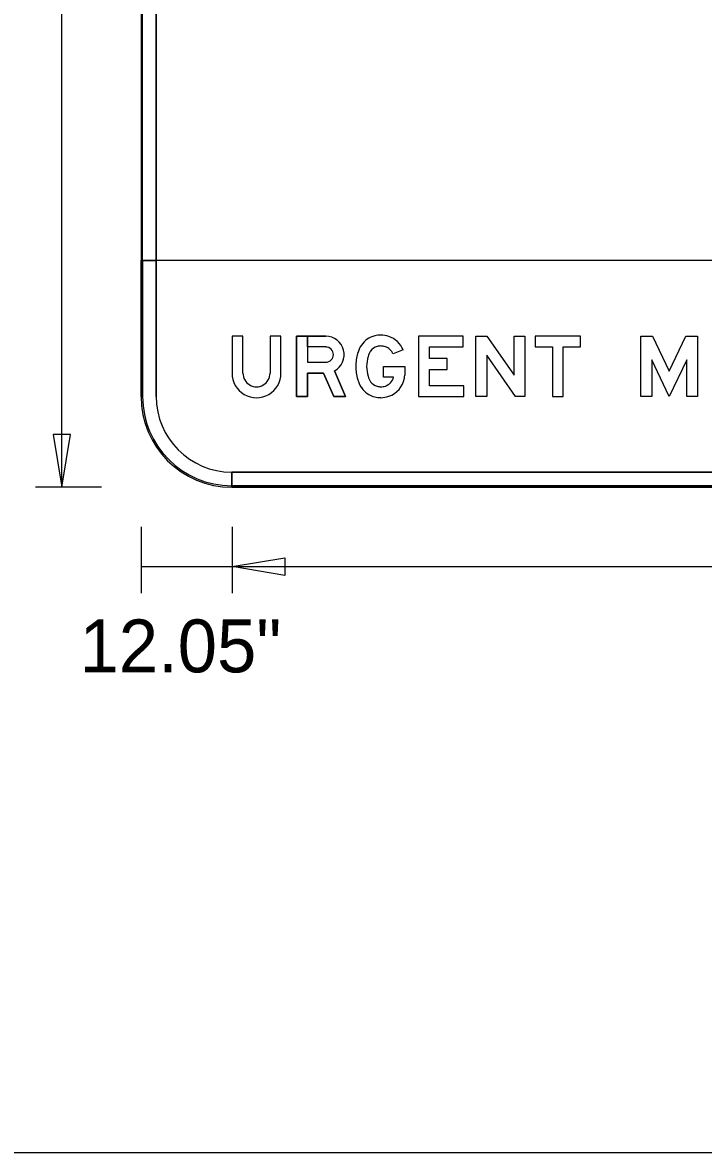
# Model space of a CAD drawing. Extents: x 17890484 to 17890754, y 17897495 to 17897992.
# Drawn here: x 17890527.22 to 17890534.74, y 17897525.52 to 17897537.98 of the extents above; entities that cross this region are included whole.
import ezdxf

# ---------------------------------------------------------------- set-up
doc = ezdxf.new("R2010")
doc.units = 0
for name, color, linetype in [('GSBWFill', 7, 'Continuous'), ('GSColorFill', 7, 'Continuous'), ('GSDims', 7, 'Continuous'), ('GSOutline', 7, 'Continuous'), ('SheetLinesMisc2_dp', 7, 'Continuous')]:
    doc.layers.add(name, color=color, linetype=linetype)

msp = doc.modelspace()

# ---------------------------------------------------------------- linework, layer by layer
at = {"layer": 'GSBWFill'}
for p, q in [((17890528.531, 17897541.854), (17890528.531, 17897533.854)), ((17890528.698, 17897533.854), (17890528.698, 17897541.854)), ((17890528.531, 17897533.854), (17890528.531, 17897535.354)), ((17890528.531, 17897535.354), (17890528.698, 17897535.354)), ((17890548.531, 17897535.354), (17890528.531, 17897535.354)), ((17890528.531, 17897535.354), (17890528.531, 17897533.854)), ((17890528.698, 17897535.354), (17890528.698, 17897535.187)), ((17890528.698, 17897535.187), (17890528.698, 17897533.854)), ((17890529.955, 17897534.521), (17890529.955, 17897534.112)), ((17890529.531, 17897532.854), (17890529.531, 17897533.021)), ((17890529.531, 17897533.021), (17890547.531, 17897533.021)), ((17890547.531, 17897533.021), (17890529.533, 17897533.021)), ((17890529.533, 17897533.021), (17890529.533, 17897532.854)), ((17890547.531, 17897532.854), (17890529.531, 17897532.854)), ((17890529.531, 17897532.854), (17890547.531, 17897532.854)), ((17890529.533, 17897532.854), (17890547.531, 17897532.854))]:
    msp.add_line(p, q, dxfattribs=at)
for points in [[(17890529.655, 17897534.112), (17890529.655, 17897534.521), (17890529.535, 17897534.521), (17890529.535, 17897534.112)], [(17890530.075, 17897534.112), (17890530.075, 17897534.521), (17890529.955, 17897534.521)], [(17890530.665, 17897534.138), (17890530.788, 17897533.854), (17890530.657, 17897533.854), (17890530.545, 17897534.114), (17890530.368, 17897534.114), (17890530.368, 17897533.854), (17890530.248, 17897533.854), (17890530.248, 17897534.521), (17890530.368, 17897534.521), (17890530.368, 17897534.234), (17890530.57, 17897534.234)], [(17890530.368, 17897534.401), (17890530.368, 17897534.521), (17890530.57, 17897534.521)], [(17890530.57, 17897534.401), (17890530.368, 17897534.401)], [(17890531.423, 17897534.37), (17890531.312, 17897534.325)], [(17890531.318, 17897534.067), (17890531.208, 17897534.067), (17890531.208, 17897534.187), (17890531.441, 17897534.187), (17890531.441, 17897534.091)]]:
    msp.add_lwpolyline(points, dxfattribs=at)
for points in [[(17890532.095, 17897533.974), (17890531.715, 17897533.974), (17890531.715, 17897534.153), (17890531.911, 17897534.153), (17890531.911, 17897534.273), (17890531.715, 17897534.273), (17890531.715, 17897534.401), (17890532.085, 17897534.401), (17890532.085, 17897534.521), (17890531.595, 17897534.521), (17890531.595, 17897533.854), (17890532.095, 17897533.854)], [(17890532.768, 17897534.521), (17890532.768, 17897533.854), (17890532.665, 17897533.854), (17890532.348, 17897534.311), (17890532.348, 17897533.854), (17890532.228, 17897533.854), (17890532.228, 17897534.521), (17890532.348, 17897534.521), (17890532.648, 17897534.089), (17890532.648, 17897534.521)], [(17890532.881, 17897534.401), (17890533.071, 17897534.401), (17890533.071, 17897533.854), (17890533.191, 17897533.854), (17890533.191, 17897534.401), (17890533.381, 17897534.401), (17890533.381, 17897534.521), (17890532.881, 17897534.521)], [(17890534.361, 17897534.134), (17890534.545, 17897534.521), (17890534.675, 17897534.521), (17890534.675, 17897533.854), (17890534.555, 17897533.854), (17890534.555, 17897534.261), (17890534.361, 17897533.854), (17890534.168, 17897534.261), (17890534.168, 17897533.854), (17890534.048, 17897533.854), (17890534.048, 17897534.521), (17890534.177, 17897534.521)]]:
    msp.add_lwpolyline(points, close=True, dxfattribs=at)
for centre, radius, start, end in [((17890530.57, 17897534.317), 0.203, 297.837, 90), ((17890530.57, 17897534.317), 0.0833, 270, 90), ((17890529.531, 17897533.854), 1, 180, 270), ((17890529.531, 17897533.854), 1, 180, 270), ((17890529.531, 17897533.854), 1, 180, 270), ((17890529.531, 17897533.854), 0.833, 180, 270), ((17890529.531, 17897533.854), 0.833, 180, 270)]:
    msp.add_arc(centre, radius, start, end, dxfattribs=at)
for centre, major_axis, start_param, end_param in [((17890531.165, 17897534.291), (0, 0.24), 0.229188, 0.990896), ((17890531.177, 17897534.243), (0, 0.289), 0, 0.229188), ((17890531.177, 17897534.252), (0, 0.28), 5.955089, 6.283185), ((17890531.183, 17897534.272), (0, 0.259), 5.097002, 5.955089), ((17890531.255, 17897534.232), (0, 0.348), 0.990896, 1.282161), ((17890531.165, 17897534.291), (0, 0.12), 0.229188, 0.990896), ((17890531.177, 17897534.243), (0, 0.169), 6.283185, 6.512373), ((17890531.177, 17897534.252), (0, 0.16), 5.955089, 6.283185), ((17890531.183, 17897534.272), (0, 0.139), 5.097002, 5.955089), ((17890531.406, 17897534.187), (0, 0.505), 1.282161, 1.570796), ((17890531.406, 17897534.187), (0, 0.385), 1.282161, 1.570796), ((17890531.255, 17897534.232), (0, 0.228), 0.990896, 1.282161), ((17890531.406, 17897534.187), (0, 0.505), 1.570796, 1.859431), ((17890531.406, 17897534.187), (0, 0.385), 1.570796, 1.859431), ((17890529.805, 17897534.112), (0, 0.27), 1.570796, 4.712389), ((17890529.805, 17897534.112), (0, 0.15), 1.570796, 4.712389), ((17890531.255, 17897534.143), (0, 0.348), 1.859431, 2.150696), ((17890531.255, 17897534.143), (0, 0.228), 1.859431, 2.150696), ((17890531.165, 17897534.084), (0, 0.12), 2.150696, 2.912405), ((17890531.183, 17897534.102), (0, 0.139), 3.469689, 4.457885), ((17890531.183, 17897534.102), (0, 0.259), 3.469689, 4.532209), ((17890531.243, 17897534.091), (0, 0.198), 4.532209, 4.712389), ((17890531.165, 17897534.084), (0, 0.24), 2.150696, 2.912405), ((17890531.177, 17897534.132), (0, 0.169), 2.912405, 3.141593), ((17890531.177, 17897534.122), (0, 0.16), 3.141593, 3.469689), ((17890531.177, 17897534.132), (0, 0.289), 2.912405, 3.141593), ((17890531.177, 17897534.122), (0, 0.28), 3.141593, 3.469689)]:
    msp.add_ellipse(centre, major_axis=major_axis, ratio=0.999994, start_param=start_param, end_param=end_param, dxfattribs=at)
at = {"layer": 'GSColorFill'}
for p, q in [((17890528.531, 17897541.854), (17890528.531, 17897533.854)), ((17890528.531, 17897541.854), (17890528.531, 17897533.854)), ((17890528.531, 17897541.854), (17890528.531, 17897533.854)), ((17890528.548, 17897533.854), (17890528.548, 17897541.854)), ((17890528.698, 17897533.854), (17890528.698, 17897541.854)), ((17890548.531, 17897535.354), (17890528.531, 17897535.354)), ((17890528.531, 17897535.354), (17890528.531, 17897533.854)), ((17890528.531, 17897533.854), (17890528.531, 17897535.354)), ((17890528.531, 17897535.354), (17890528.698, 17897535.354)), ((17890528.531, 17897533.854), (17890528.531, 17897535.354)), ((17890528.531, 17897535.354), (17890528.548, 17897535.354)), ((17890528.548, 17897535.354), (17890528.548, 17897535.337)), ((17890528.548, 17897535.337), (17890528.548, 17897533.854)), ((17890528.698, 17897535.354), (17890528.698, 17897535.187)), ((17890528.698, 17897535.187), (17890528.698, 17897533.854)), ((17890529.955, 17897534.521), (17890529.955, 17897534.112)), ((17890529.531, 17897532.854), (17890529.531, 17897533.021)), ((17890529.531, 17897533.021), (17890547.531, 17897533.021)), ((17890547.531, 17897533.021), (17890529.533, 17897533.021)), ((17890529.533, 17897533.021), (17890529.533, 17897532.854)), ((17890529.531, 17897532.854), (17890529.531, 17897532.871)), ((17890547.531, 17897532.871), (17890529.531, 17897532.871)), ((17890529.531, 17897532.871), (17890529.531, 17897532.854)), ((17890529.531, 17897532.871), (17890547.531, 17897532.871)), ((17890529.531, 17897532.854), (17890547.531, 17897532.854)), ((17890529.531, 17897532.854), (17890547.531, 17897532.854)), ((17890529.531, 17897532.854), (17890547.531, 17897532.854)), ((17890547.531, 17897532.854), (17890529.531, 17897532.854)), ((17890547.531, 17897532.854), (17890529.531, 17897532.854)), ((17890529.533, 17897532.854), (17890547.531, 17897532.854))]:
    msp.add_line(p, q, dxfattribs=at)
for points in [[(17890529.655, 17897534.112), (17890529.655, 17897534.521), (17890529.535, 17897534.521), (17890529.535, 17897534.112)], [(17890530.075, 17897534.112), (17890530.075, 17897534.521), (17890529.955, 17897534.521)], [(17890530.665, 17897534.138), (17890530.788, 17897533.854), (17890530.657, 17897533.854), (17890530.545, 17897534.114), (17890530.368, 17897534.114), (17890530.368, 17897533.854), (17890530.248, 17897533.854), (17890530.248, 17897534.521), (17890530.368, 17897534.521), (17890530.368, 17897534.234), (17890530.57, 17897534.234)], [(17890530.368, 17897534.401), (17890530.368, 17897534.521), (17890530.57, 17897534.521)], [(17890530.57, 17897534.401), (17890530.368, 17897534.401)], [(17890531.423, 17897534.37), (17890531.312, 17897534.325)], [(17890531.318, 17897534.067), (17890531.208, 17897534.067), (17890531.208, 17897534.187), (17890531.441, 17897534.187), (17890531.441, 17897534.091)]]:
    msp.add_lwpolyline(points, dxfattribs=at)
for points in [[(17890532.095, 17897533.974), (17890531.715, 17897533.974), (17890531.715, 17897534.153), (17890531.911, 17897534.153), (17890531.911, 17897534.273), (17890531.715, 17897534.273), (17890531.715, 17897534.401), (17890532.085, 17897534.401), (17890532.085, 17897534.521), (17890531.595, 17897534.521), (17890531.595, 17897533.854), (17890532.095, 17897533.854)], [(17890532.768, 17897534.521), (17890532.768, 17897533.854), (17890532.665, 17897533.854), (17890532.348, 17897534.311), (17890532.348, 17897533.854), (17890532.228, 17897533.854), (17890532.228, 17897534.521), (17890532.348, 17897534.521), (17890532.648, 17897534.089), (17890532.648, 17897534.521)], [(17890532.881, 17897534.401), (17890533.071, 17897534.401), (17890533.071, 17897533.854), (17890533.191, 17897533.854), (17890533.191, 17897534.401), (17890533.381, 17897534.401), (17890533.381, 17897534.521), (17890532.881, 17897534.521)], [(17890534.361, 17897534.134), (17890534.545, 17897534.521), (17890534.675, 17897534.521), (17890534.675, 17897533.854), (17890534.555, 17897533.854), (17890534.555, 17897534.261), (17890534.361, 17897533.854), (17890534.168, 17897534.261), (17890534.168, 17897533.854), (17890534.048, 17897533.854), (17890534.048, 17897534.521), (17890534.177, 17897534.521)]]:
    msp.add_lwpolyline(points, close=True, dxfattribs=at)
for centre, radius, start, end in [((17890530.57, 17897534.317), 0.203, 297.837, 90), ((17890530.57, 17897534.317), 0.0833, 270, 90), ((17890529.531, 17897533.854), 1, 180, 270), ((17890529.531, 17897533.854), 1, 180, 270), ((17890529.531, 17897533.854), 1, 180, 270), ((17890529.531, 17897533.854), 1, 180, 270), ((17890529.531, 17897533.854), 1, 180, 270), ((17890529.531, 17897533.854), 1, 180, 270), ((17890529.531, 17897533.854), 0.983, 180, 270), ((17890529.531, 17897533.854), 0.983, 180, 270), ((17890529.531, 17897533.854), 0.833, 180, 270), ((17890529.531, 17897533.854), 0.833, 180, 270)]:
    msp.add_arc(centre, radius, start, end, dxfattribs=at)
for centre, major_axis, start_param, end_param in [((17890531.165, 17897534.291), (0, 0.24), 0.229188, 0.990896), ((17890531.177, 17897534.243), (0, 0.289), 0, 0.229188), ((17890531.177, 17897534.252), (0, 0.28), 5.955089, 6.283185), ((17890531.183, 17897534.272), (0, 0.259), 5.097002, 5.955089), ((17890531.255, 17897534.232), (0, 0.348), 0.990896, 1.282161), ((17890531.165, 17897534.291), (0, 0.12), 0.229188, 0.990896), ((17890531.177, 17897534.243), (0, 0.169), 6.283185, 6.512373), ((17890531.177, 17897534.252), (0, 0.16), 5.955089, 6.283185), ((17890531.183, 17897534.272), (0, 0.139), 5.097002, 5.955089), ((17890531.406, 17897534.187), (0, 0.505), 1.282161, 1.570796), ((17890531.406, 17897534.187), (0, 0.385), 1.282161, 1.570796), ((17890531.255, 17897534.232), (0, 0.228), 0.990896, 1.282161), ((17890531.406, 17897534.187), (0, 0.505), 1.570796, 1.859431), ((17890531.406, 17897534.187), (0, 0.385), 1.570796, 1.859431), ((17890529.805, 17897534.112), (0, 0.27), 1.570796, 4.712389), ((17890529.805, 17897534.112), (0, 0.15), 1.570796, 4.712389), ((17890531.255, 17897534.143), (0, 0.348), 1.859431, 2.150696), ((17890531.255, 17897534.143), (0, 0.228), 1.859431, 2.150696), ((17890531.165, 17897534.084), (0, 0.12), 2.150696, 2.912405), ((17890531.183, 17897534.102), (0, 0.139), 3.469689, 4.457885), ((17890531.183, 17897534.102), (0, 0.259), 3.469689, 4.532209), ((17890531.243, 17897534.091), (0, 0.198), 4.532209, 4.712389), ((17890531.165, 17897534.084), (0, 0.24), 2.150696, 2.912405), ((17890531.177, 17897534.132), (0, 0.169), 2.912405, 3.141593), ((17890531.177, 17897534.122), (0, 0.16), 3.141593, 3.469689), ((17890531.177, 17897534.132), (0, 0.289), 2.912405, 3.141593), ((17890531.177, 17897534.122), (0, 0.28), 3.141593, 3.469689)]:
    msp.add_ellipse(centre, major_axis=major_axis, ratio=0.999994, start_param=start_param, end_param=end_param, dxfattribs=at)
at = {"layer": 'GSDims'}
for p, q in [((17890527.656, 17897532.854), (17890527.656, 17897542.854)), ((17890528.094, 17897532.854), (17890527.365, 17897532.854)), ((17890528.531, 17897532.417), (17890528.531, 17897531.687)), ((17890529.535, 17897532.417), (17890529.535, 17897531.687)), ((17890529.535, 17897532.417), (17890529.535, 17897531.687)), ((17890528.531, 17897531.979), (17890529.535, 17897531.979)), ((17890529.535, 17897531.979), (17890547.528, 17897531.979))]:
    msp.add_line(p, q, dxfattribs=at)
for points in [[(17890527.656, 17897532.854), (17890527.753, 17897533.437), (17890527.559, 17897533.437)], [(17890529.535, 17897531.979), (17890530.118, 17897532.076), (17890530.118, 17897531.882)]]:
    msp.add_lwpolyline(points, close=True, dxfattribs=at)
at = {"layer": 'GSOutline'}
for p, q in [((17890528.531, 17897541.854), (17890528.531, 17897533.854)), ((17890528.698, 17897541.854), (17890528.698, 17897533.854)), ((17890528.531, 17897533.854), (17890528.531, 17897535.354)), ((17890528.531, 17897535.354), (17890528.698, 17897535.354)), ((17890548.531, 17897535.354), (17890528.531, 17897535.354)), ((17890528.531, 17897535.354), (17890528.531, 17897533.854)), ((17890528.698, 17897535.354), (17890528.698, 17897535.187)), ((17890528.698, 17897535.187), (17890528.698, 17897533.854)), ((17890529.955, 17897534.521), (17890529.955, 17897534.112)), ((17890529.531, 17897533.021), (17890547.531, 17897533.021)), ((17890529.531, 17897533.021), (17890547.531, 17897533.021)), ((17890529.531, 17897532.854), (17890547.531, 17897532.854)), ((17890547.531, 17897532.854), (17890529.531, 17897532.854)), ((17890529.531, 17897532.854), (17890547.531, 17897532.854))]:
    msp.add_line(p, q, dxfattribs=at)
for points in [[(17890529.655, 17897534.112), (17890529.655, 17897534.521), (17890529.535, 17897534.521), (17890529.535, 17897534.112)], [(17890530.075, 17897534.112), (17890530.075, 17897534.521), (17890529.955, 17897534.521)], [(17890530.57, 17897534.521), (17890530.248, 17897534.521), (17890530.248, 17897533.854), (17890530.368, 17897533.854), (17890530.368, 17897534.114), (17890530.545, 17897534.114), (17890530.657, 17897533.854), (17890530.788, 17897533.854), (17890530.665, 17897534.138)], [(17890530.57, 17897534.401), (17890530.368, 17897534.401), (17890530.368, 17897534.234), (17890530.57, 17897534.234)], [(17890531.423, 17897534.37), (17890531.312, 17897534.325)], [(17890531.318, 17897534.067), (17890531.208, 17897534.067), (17890531.208, 17897534.187), (17890531.441, 17897534.187), (17890531.441, 17897534.091)]]:
    msp.add_lwpolyline(points, dxfattribs=at)
for points in [[(17890532.095, 17897533.974), (17890531.715, 17897533.974), (17890531.715, 17897534.153), (17890531.911, 17897534.153), (17890531.911, 17897534.273), (17890531.715, 17897534.273), (17890531.715, 17897534.401), (17890532.085, 17897534.401), (17890532.085, 17897534.521), (17890531.595, 17897534.521), (17890531.595, 17897533.854), (17890532.095, 17897533.854)], [(17890532.768, 17897534.521), (17890532.768, 17897533.854), (17890532.665, 17897533.854), (17890532.348, 17897534.311), (17890532.348, 17897533.854), (17890532.228, 17897533.854), (17890532.228, 17897534.521), (17890532.348, 17897534.521), (17890532.648, 17897534.089), (17890532.648, 17897534.521)], [(17890532.881, 17897534.401), (17890533.071, 17897534.401), (17890533.071, 17897533.854), (17890533.191, 17897533.854), (17890533.191, 17897534.401), (17890533.381, 17897534.401), (17890533.381, 17897534.521), (17890532.881, 17897534.521)], [(17890534.361, 17897534.134), (17890534.545, 17897534.521), (17890534.675, 17897534.521), (17890534.675, 17897533.854), (17890534.555, 17897533.854), (17890534.555, 17897534.261), (17890534.361, 17897533.854), (17890534.168, 17897534.261), (17890534.168, 17897533.854), (17890534.048, 17897533.854), (17890534.048, 17897534.521), (17890534.177, 17897534.521)]]:
    msp.add_lwpolyline(points, close=True, dxfattribs=at)
for centre, radius, start, end in [((17890530.57, 17897534.317), 0.203, 297.837, 90), ((17890530.57, 17897534.317), 0.0833, 270, 90), ((17890529.531, 17897533.854), 1, 180, 270), ((17890529.531, 17897533.854), 1, 180, 270), ((17890529.531, 17897533.854), 1, 180, 270), ((17890529.531, 17897533.854), 0.833, 180, 270), ((17890529.531, 17897533.854), 0.833, 180, 270)]:
    msp.add_arc(centre, radius, start, end, dxfattribs=at)
for centre, major_axis, start_param, end_param in [((17890531.165, 17897534.291), (0, 0.24), 0.229188, 0.990896), ((17890531.177, 17897534.243), (0, 0.289), 0, 0.229188), ((17890531.177, 17897534.252), (0, 0.28), 5.955089, 6.283185), ((17890531.183, 17897534.272), (0, 0.259), 5.097002, 5.955089), ((17890531.255, 17897534.232), (0, 0.348), 0.990896, 1.282161), ((17890531.165, 17897534.291), (0, 0.12), 0.229188, 0.990896), ((17890531.177, 17897534.243), (0, 0.169), 6.283185, 6.512373), ((17890531.177, 17897534.252), (0, 0.16), 5.955089, 6.283185), ((17890531.183, 17897534.272), (0, 0.139), 5.097002, 5.955089), ((17890531.406, 17897534.187), (0, 0.505), 1.282161, 1.570796), ((17890531.406, 17897534.187), (0, 0.385), 1.282161, 1.570796), ((17890531.255, 17897534.232), (0, 0.228), 0.990896, 1.282161), ((17890531.406, 17897534.187), (0, 0.505), 1.570796, 1.859431), ((17890531.406, 17897534.187), (0, 0.385), 1.570796, 1.859431), ((17890529.805, 17897534.112), (0, 0.27), 1.570796, 4.712389), ((17890529.805, 17897534.112), (0, 0.15), 1.570796, 4.712389), ((17890531.255, 17897534.143), (0, 0.348), 1.859431, 2.150696), ((17890531.255, 17897534.143), (0, 0.228), 1.859431, 2.150696), ((17890531.165, 17897534.084), (0, 0.12), 2.150696, 2.912405), ((17890531.183, 17897534.102), (0, 0.139), 3.469689, 4.457885), ((17890531.183, 17897534.102), (0, 0.259), 3.469689, 4.532209), ((17890531.243, 17897534.091), (0, 0.198), 4.532209, 4.712389), ((17890531.165, 17897534.084), (0, 0.24), 2.150696, 2.912405), ((17890531.177, 17897534.132), (0, 0.169), 2.912405, 3.141593), ((17890531.177, 17897534.122), (0, 0.16), 3.141593, 3.469689), ((17890531.177, 17897534.132), (0, 0.289), 2.912405, 3.141593), ((17890531.177, 17897534.122), (0, 0.28), 3.141593, 3.469689)]:
    msp.add_ellipse(centre, major_axis=major_axis, ratio=0.999994, start_param=start_param, end_param=end_param, dxfattribs=at)
at = {"layer": 'SheetLinesMisc2_dp'}
msp.add_line((17890512.958, 17897525.517), (17890564.13, 17897525.517), dxfattribs=at)

# ---------------------------------------------------------------- texts
at = {"layer": 'GSDims'}
msp.add_text('12.05"', height=0.5833, dxfattribs=at).set_placement((17890527.851, 17897530.812))

doc.saveas('drawing.dxf')
